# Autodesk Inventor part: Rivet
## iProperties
Author: Flavien MARTY
Shininess: 60.0
PropertySet Name: _Private Model Information
Created: 2001-10
Part Number: Rivet
Material: Par défaut
Document SubType Name: Modélisation
Designer: Flavien MARTY
Control State: 0
Master: False
Checked Out: False
PropertySet Name: Design Tracking Control
Density: 0.0
Volumn: 0.0
Area: 0.0
PropertySet Name: Model Information
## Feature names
1. Base1
